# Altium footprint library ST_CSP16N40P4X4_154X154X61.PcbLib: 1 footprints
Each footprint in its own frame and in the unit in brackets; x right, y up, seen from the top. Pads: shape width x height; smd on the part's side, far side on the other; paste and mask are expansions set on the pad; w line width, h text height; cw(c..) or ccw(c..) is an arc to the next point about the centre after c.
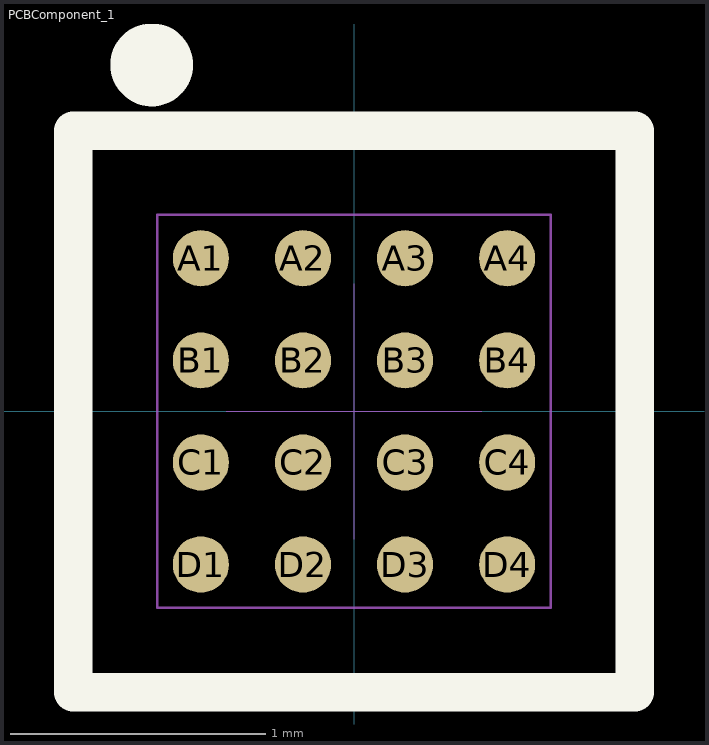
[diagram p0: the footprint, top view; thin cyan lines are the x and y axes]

## PCBComponent_1 [mm]
pads (16):
  round 0.22 smd paste-20 mask+0.04: A1(-0.6,0.6) A2(-0.2,0.6) A3(0.2,0.6) A4(0.6,0.6) B1(-0.6,0.2) B2(-0.2,0.2) B3(0.2,0.2) B4(0.6,0.2) C1(-0.6,-0.2) C2(-0.2,-0.2) C3(0.2,-0.2) C4(0.6,-0.2) D1(-0.6,-0.6) D2(-0.2,-0.6) D3(0.2,-0.6) D4(0.6,-0.6)
Top Overlay:
  circle w0.254: c-0.792,1.358 r0.035
  lines w0.15: -1.1,-1.1 1.1,-1.1 1.1,1.1 -1.1,1.1 -1.1,-1.1
Top Paste:
  rectangle: -0.31,-0.71 -0.09,-0.49
  rectangle: 0.09,-0.71 0.31,-0.49
  rectangle: 0.49,-0.71 0.71,-0.49
  rectangle: 0.49,-0.31 0.71,-0.09
  rectangle: 0.09,-0.31 0.31,-0.09
  rectangle: -0.31,-0.31 -0.09,-0.09
  rectangle: -0.31,0.09 -0.09,0.31
  rectangle: 0.09,0.09 0.31,0.31
  rectangle: 0.49,0.09 0.71,0.31
  rectangle: 0.49,0.49 0.71,0.71
  rectangle: 0.09,0.49 0.31,0.71
  rectangle: -0.31,0.49 -0.09,0.71
  rectangle: -0.71,-0.71 -0.49,-0.49
  rectangle: -0.71,-0.31 -0.49,-0.09
  rectangle: -0.71,0.09 -0.49,0.31
  rectangle: -0.71,0.49 -0.49,0.71
Mechanical 15:
  lines w0.001: -0.5,0 0.5,0 ; 0,-0.5 0,0.5
  lines w0.01: -0.77,-0.77 -0.77,0.77 0.77,0.77 0.77,-0.77 -0.77,-0.77
3D body: height 0.61, standoff 0.26, extent -0.77,-0.77 0.77,0.77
